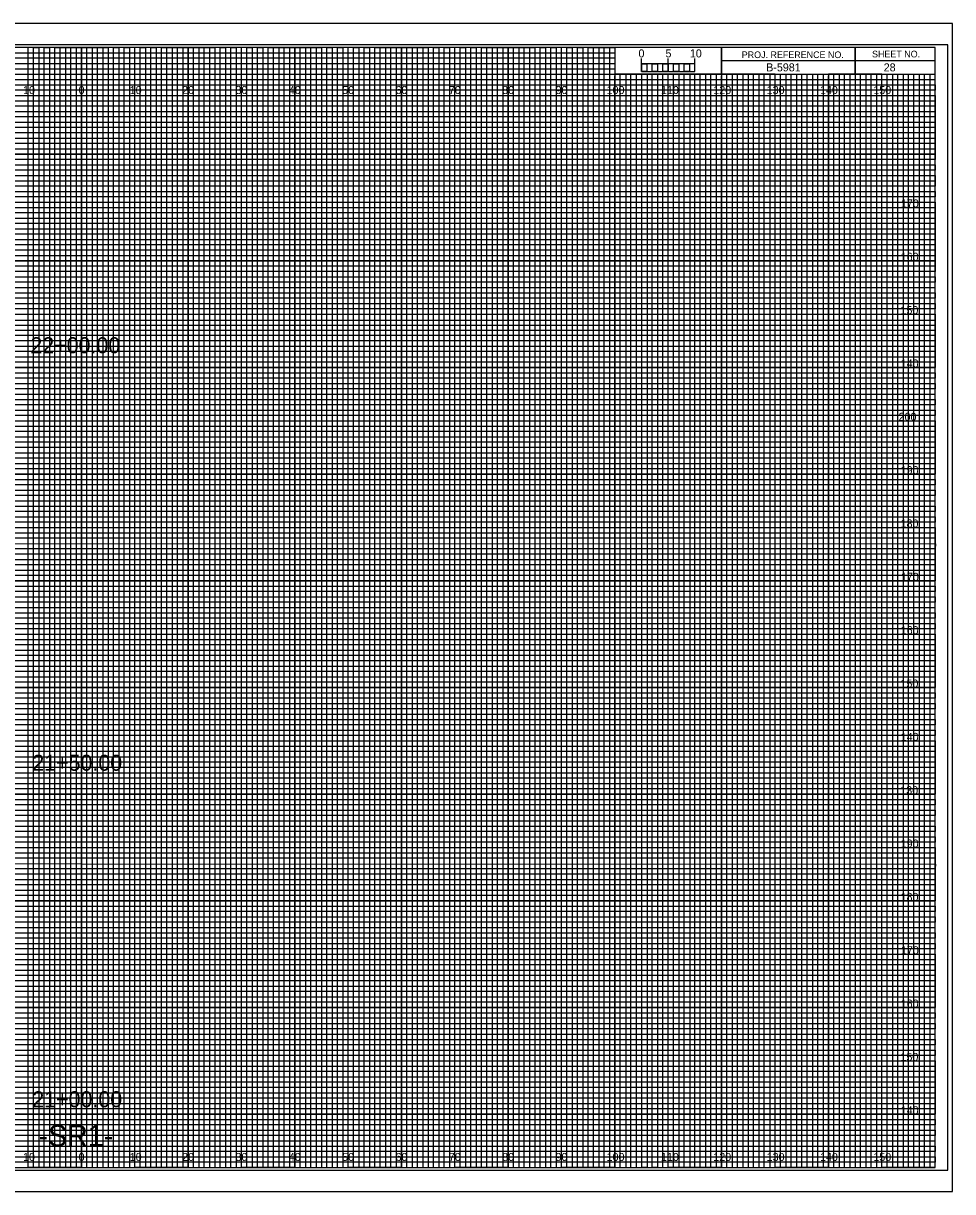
# Model space of a CAD drawing. Extents: x -13 to 323, y -5 to 654.
# Drawn here: x 149.1 to 323.3, y -4.5 to 214.5 of the extents above; entities that cross this region are included whole.
import ezdxf

# ---------------------------------------------------------------- set-up
doc = ezdxf.new("R2010")
doc.units = 0
for name, color, linetype in [('Exist Cross Section Cell', 7, 'Continuous'), ('Exist XS Center Line Elevation Label', 7, 'Continuous'), ('Exist XS Ground Line', 7, 'Continuous'), ('Prop CMT Concrete Structures', 7, 'Continuous'), ('Prop CMT Guardrail Graphics', 7, 'Continuous'), ('Prop CMT Pvmt Course 1', 7, 'Continuous'), ('Prop CMT Pvmt Course 2', 7, 'Continuous'), ('Prop CMT Pvmt Course 3', 7, 'Continuous'), ('Prop CMT Pvmt Surface', 7, 'Continuous'), ('Prop CMT Shld Paved Course 1', 7, 'Continuous'), ('Prop CMT Shld Paved Course 2', 7, 'Continuous'), ('Prop CMT Shld Paved Course 3', 7, 'Continuous'), ('Prop CMT Subgrade Earthwork', 7, 'Continuous'), ('Prop XS Ditch Standard Text', 7, 'Continuous'), ('Prop XS SE Text', 7, 'Continuous'), ('Prop XS Side Slope Text', 7, 'Continuous'), ('Scratch_Level_0', 7, 'Continuous')]:
    doc.layers.add(name, color=color, linetype=linetype)

msp = doc.modelspace()

# ---------------------------------------------------------------- linework, layer by layer
at = {"layer": 'Exist XS Center Line Elevation Label'}
for points in [[(145, 0), (155, 0), (155, 210), (165, 210), (165, 0), (175, 0), (175, 210), (185, 210), (185, 0), (195, 0), (195, 210), (205, 210), (205, 0), (215, 0), (215, 210), (225, 210), (225, 0), (235, 0), (235, 210), (245, 210), (245, 0), (255, 0), (255, 210), (259.93, 210), (260, 210), (260, 205), (264.99, 205), (264.99, 0), (275, 0), (275, 205), (285, 205), (285, 0), (295, 0), (295, 205), (305, 205), (305, 0), (315, 0), (315, 205)], [(0, 205), (275, 205)], [(0, 185), (320, 185), (320, 195), (0, 195)], [(0, 165), (320, 165), (320, 175), (0, 175)], [(0, 145), (320, 145), (320, 155), (0, 155)], [(0, 125), (320, 125), (320, 135), (0, 135)], [(0, 105), (320, 105), (320, 115), (0, 115)], [(0, 85), (320, 85), (320, 95), (0, 95)], [(0, 65), (320, 65), (320, 75), (0, 75)], [(0, 45), (320, 45), (320, 55), (0, 55)], [(0, 25), (320, 25), (320, 35), (0, 35)], [(0, 5), (320, 5), (320, 15), (0, 15)]]:
    msp.add_lwpolyline(points, dxfattribs=at)
at = {"layer": 'Exist XS Ground Line'}
for p, q in [((150, 210), (140, 210)), ((150, 0), (150, 210)), ((170, 210), (160, 210)), ((160, 210), (160, 0)), ((170, 0), (170, 210)), ((190, 210), (180, 210)), ((180, 210), (180, 0)), ((190, 0), (190, 210)), ((210, 210), (200, 210)), ((200, 210), (200, 0)), ((210, 0), (210, 210)), ((230, 210), (220, 210)), ((220, 210), (220, 0)), ((230, 0), (230, 210)), ((250, 210), (240, 210)), ((240, 210), (240, 0)), ((250, 0), (250, 210)), ((260, 210), (260, 0)), ((270, 0), (270, 205)), ((290, 205), (280, 205)), ((280, 205), (280, 0)), ((290, 0), (290, 205)), ((310, 205), (300, 205)), ((300, 205), (300, 0)), ((310, 0), (310, 205)), ((160, 0), (150, 0)), ((180, 0), (170, 0)), ((200, 0), (190, 0)), ((220, 0), (210, 0)), ((240, 0), (230, 0)), ((260, 0), (250, 0)), ((280, 0), (270, 0)), ((300, 0), (290, 0)), ((320, 0), (310, 0)), ((320, 0), (320, 0))]:
    msp.add_line(p, q, dxfattribs=at)
for points in [[(0, 200), (320, 200), (320, 190), (0, 190)], [(0, 180), (320, 180), (320, 170), (0, 170)], [(0, 160), (320, 160), (320, 150), (0, 150)], [(0, 140), (320, 140), (320, 130), (0, 130)], [(0, 120), (320, 120), (320, 110), (0, 110)], [(0, 100), (320, 100), (320, 90), (0, 90)], [(0, 80), (320, 80), (320, 70), (0, 70)], [(0, 60), (320, 60), (320, 50), (0, 50)], [(0, 40), (320, 40), (320, 30), (0, 30)], [(0, 20), (320, 20), (320, 10), (0, 10)]]:
    msp.add_lwpolyline(points, dxfattribs=at)
at = {"layer": 'Prop CMT Pvmt Course 1'}
for p, q in [((323.3, 214.5), (-13.4, 214.5)), ((-13.4, -4.5), (323.3, -4.5))]:
    msp.add_line(p, q, dxfattribs=at)
at = {"layer": 'Prop CMT Pvmt Course 2'}
msp.add_lwpolyline([(-13.4, -4.5), (323.3, -4.5), (323.3, 214.5), (-13.4, 214.5)], close=True, dxfattribs=at)
at = {"layer": 'Prop CMT Pvmt Course 3'}
msp.add_lwpolyline([(-10.8, -0.5), (322.4, -0.5), (322.4, 210.5), (-10.8, 210.5)], close=True, dxfattribs=at)
at = {"layer": 'Prop CMT Shld Paved Course 1'}
for p, q in [((305, 210), (305, 205)), ((305, 205), (305, 210)), ((280, 207.5), (280, 205)), ((320, 207.49), (280, 207.49)), ((280, 205), (320, 205))]:
    msp.add_line(p, q, dxfattribs=at)
for points in [[(320, 210), (0, 210), (0, 0), (320, 0)], [(280, 210), (260, 210), (260, 205.03), (280, 205.03)], [(320, 210), (280, 210), (280, 205), (320, 205)]]:
    msp.add_lwpolyline(points, close=True, dxfattribs=at)
at = {"layer": 'Prop CMT Shld Paved Course 2'}
for p, q in [((267, 205), (266.01, 205)), ((266.01, 205), (266.01, 0)), ((267, 0), (267, 205)), ((269, 205), (268, 205)), ((268, 205), (268, 0)), ((269, 0), (269, 205)), ((266.01, 0), (265, 0)), ((268, 0), (267, 0))]:
    msp.add_line(p, q, dxfattribs=at)
for points in [[(150, 0), (151, 0), (151, 210), (152, 210), (152, 0)], [(152, 0), (153, 0), (153, 210), (154, 210), (154, 0)], [(155, 0), (156, 0), (156, 210), (157, 210), (157, 0)], [(157, 0), (158, 0), (158, 210), (159, 210), (159, 0)], [(160, 0), (161, 0), (161, 210), (162, 210), (162, 0)], [(162, 0), (163, 0), (163, 210), (164, 210), (164, 0)], [(165, 0), (166, 0), (166, 210), (167, 210), (167, 0)], [(167, 0), (168, 0), (168, 210), (169, 210), (169, 0)], [(170, 0), (171, 0), (171, 210), (172, 210), (172, 0)], [(172, 0), (173, 0), (173, 210), (174, 210), (174, 0)], [(175, 0), (176, 0), (176, 210), (177, 210), (177, 0)], [(177, 0), (178, 0), (178, 210), (179, 210), (179, 0)], [(180, 0), (181, 0), (181, 210), (182, 210), (182, 0)], [(182, 0), (183, 0), (183, 210), (184, 210), (184, 0)], [(185, 0), (186, 0), (186, 210), (187, 210), (187, 0)], [(187, 0), (188, 0), (188, 210), (189, 210), (189, 0)], [(190, 0), (191, 0), (191, 210), (192, 210), (192, 0)], [(192, 0), (193, 0), (193, 210), (194, 210), (194, 0)], [(195, 0), (196, 0), (196, 210), (197, 210), (197, 0)], [(197, 0), (198, 0), (198, 210), (199, 210), (199, 0)], [(200, 0), (201, 0), (201, 210), (202, 210), (202, 0)], [(202, 0), (203, 0), (203, 210), (204, 210), (204, 0)], [(205, 0), (206, 0), (206, 210), (207, 210), (207, 0)], [(207, 0), (208, 0), (208, 210), (209, 210), (209, 0)], [(210, 0), (211, 0), (211, 210), (212, 210), (212, 0)], [(212, 0), (213, 0), (213, 210), (214, 210), (214, 0)], [(215, 0), (216, 0), (216, 210), (217, 210), (217, 0)], [(217, 0), (218, 0), (218, 210), (219, 210), (219, 0)], [(220, 0), (221, 0), (221, 210), (222, 210), (222, 0)], [(222, 0), (223, 0), (223, 210), (224, 210), (224, 0)], [(225, 0), (226, 0), (226, 210), (227, 210), (227, 0)], [(227, 0), (228, 0), (228, 210), (229, 210), (229, 0)], [(230, 0), (231, 0), (231, 210), (232, 210), (232, 0)], [(232, 0), (233, 0), (233, 210), (234, 210), (234, 0)], [(235, 0), (236, 0), (236, 210), (237, 210), (237, 0)], [(237, 0), (238, 0), (238, 210), (239, 210), (239, 0)], [(240, 0), (241, 0), (241, 210), (242, 210), (242, 0)], [(242, 0), (243, 0), (243, 210), (244, 210), (244, 0)], [(245, 0), (246, 0), (246, 210), (247, 210), (247, 0)], [(247, 0), (248, 0), (248, 210), (249, 210), (249, 0)], [(250, 0), (251, 0), (251, 210), (252, 210), (252, 0)], [(252, 0), (253, 0), (253, 210), (254, 210), (254, 0)], [(255, 0), (256, 0), (256, 210), (257, 210), (257, 0)], [(257, 0), (258, 0), (258, 210), (259, 210), (259, 0)], [(260, 0), (261, 0), (261, 205), (262.02, 205), (262.02, 0)], [(262, 0), (263, 0), (263, 205), (263.99, 205), (263.99, 0)], [(270, 0), (270.98, 0), (270.98, 205), (272, 205), (272, 0)], [(272, 0), (273, 0), (273, 205), (274.05, 205), (274.05, 0)], [(275, 0), (276, 0), (276, 205), (277, 205), (277, 0)], [(277, 0), (278, 0), (278, 205), (279, 205), (279, 0)], [(280, 0), (281, 0), (281, 205), (282, 205), (282, 0)], [(282, 0), (283, 0), (283, 205), (284, 205), (284, 0)], [(285, 0), (286, 0), (286, 205), (287, 205), (287, 0)], [(287, 0), (288, 0), (288, 205), (289, 205), (289, 0)], [(290, 0), (291, 0), (291, 205), (292, 205), (292, 0)], [(292, 0), (293, 0), (293, 205), (294, 205), (294, 0)], [(295, 0), (296, 0), (296, 205), (297, 205), (297, 0)], [(297, 0), (298, 0), (298, 205), (299, 205), (299, 0)], [(300, 0), (301, 0), (301, 205), (302, 205), (302, 0)], [(302, 0), (303, 0), (303, 205), (304, 205), (304, 0)], [(305, 0), (306, 0), (306, 205), (307, 205), (307, 0)], [(307, 0), (308, 0), (308, 205), (309, 205), (309, 0)], [(310, 0), (311, 0), (311, 205), (312, 205), (312, 0)], [(312, 0), (313, 0), (313, 205), (314, 205), (314, 0)], [(315, 0), (316, 0), (316, 205), (317, 205), (317, 0)], [(317, 0), (318, 0), (318, 205), (319, 205), (319, 0)]]:
    msp.add_lwpolyline(points, dxfattribs=at)
at = {"layer": 'Prop CMT Shld Paved Course 3'}
for p, q in [((265, 205.49), (265, 207.9)), ((265, 206.9), (265, 207.9)), ((270, 205.49), (270, 207.9)), ((275, 205.49), (275, 207.9)), ((275, 206.9), (275, 207.9))]:
    msp.add_line(p, q, dxfattribs=at)
for points in [[(275, 206.9), (265, 206.9), (265, 205.49), (275, 205.49)], [(265, 206.9), (266, 206.9), (266, 205.49), (265, 205.49)], [(267, 206.9), (268, 206.9), (268, 205.49), (267, 205.49)], [(269, 206.9), (270, 206.9), (270, 205.49), (269, 205.49)], [(271, 206.9), (272, 206.9), (272, 205.49), (271, 205.49)], [(273, 206.9), (274, 206.9), (274, 205.49), (273, 205.49)]]:
    msp.add_lwpolyline(points, close=True, dxfattribs=at)
at = {"layer": 'Prop CMT Subgrade Earthwork'}
for p, q in [((150, 0), (150, 210)), ((160, 0), (160, 210)), ((170, 0), (170, 210)), ((180, 0), (180, 210)), ((190, 0), (190, 210)), ((200, 0), (200, 210)), ((210, 0), (210, 210)), ((220, 0), (220, 210)), ((230, 0), (230, 210)), ((240, 0), (240, 210)), ((250, 0), (250, 210)), ((260, 0), (260, 204.69)), ((270, 0), (270, 204.69)), ((280, 0), (280, 204.69)), ((290, 0), (290, 204.69)), ((300, 0), (300, 204.69)), ((310, 0), (310, 204.69)), ((0, 200), (320, 200)), ((0, 190), (320, 190)), ((0, 180), (320, 180)), ((0, 170), (320, 170)), ((0, 160), (320, 160)), ((0, 150), (320, 150)), ((0, 140), (320, 140)), ((0, 130), (320, 130)), ((0, 120), (320, 120)), ((0, 110), (320, 110)), ((0, 100), (320, 100)), ((0, 90), (320, 90)), ((0, 80), (320, 80)), ((0, 70), (320, 70)), ((0, 60), (320, 60)), ((0, 50), (320, 50)), ((0, 40), (320, 40)), ((0, 30), (320, 30)), ((0, 20), (320, 20)), ((0, 10), (320, 10))]:
    msp.add_line(p, q, dxfattribs=at)
at = {"layer": 'Scratch_Level_0'}
for p, q in [((0, 209), (260, 209)), ((260, 209), (260, 207.98)), ((260, 207.98), (0, 207.98)), ((0, 207), (260, 207)), ((260, 205.89), (0, 205.89)), ((260, 207), (260, 205.89)), ((0, 204), (320, 204))]:
    msp.add_line(p, q, dxfattribs=at)
for points in [[(0, 203), (270, 203), (320, 203), (320, 202), (0, 202)], [(0, 201), (320, 201), (320, 199), (0, 199)], [(0, 198), (320, 198), (320, 197), (0, 196.98)], [(0, 196), (320, 196), (320, 194), (0, 194)], [(0, 193), (320, 193), (320, 192), (0, 192)], [(0, 191), (320, 191), (320, 189), (0, 189)], [(0, 188), (320, 188), (320, 187), (0, 187)], [(0, 186), (320, 186), (320, 184), (0, 184)], [(0, 183), (320, 183), (320, 182), (0, 182)], [(0, 181), (320, 181), (320, 179), (0, 179)], [(0, 178), (320, 178), (320, 177), (0, 177)], [(0, 176), (320, 176), (320, 173.95), (320, 173), (320, 172), (0, 172)], [(0, 174), (320, 174), (320, 173), (0, 173)], [(0, 171), (320, 171), (320, 169), (0, 169.03)], [(0, 169.03), (320, 169), (320, 168), (0, 168)], [(0, 167), (320, 167), (320, 166), (0, 166)], [(0, 164), (320, 164), (320, 163), (0, 163)], [(0, 162), (320, 162), (320, 161), (0, 161)], [(-0.07, 158.89), (320, 158.89), (320, 157.88), (-0.07, 157.88)], [(0, 157), (320, 157), (320, 156), (0, 156)], [(0, 154), (320, 154), (320, 153), (0, 153)], [(0, 152), (320, 152), (320, 151), (0, 151)], [(0, 149), (320, 149), (320, 148), (0, 148)], [(0, 147), (320, 147), (320, 146), (0, 146)], [(0, 144), (320, 144), (320, 143), (0, 143)], [(0, 142), (320, 142), (320, 141), (0, 141)], [(0, 139), (320, 139), (319.99, 137.98), (0, 138)], [(0, 137), (320, 137), (320, 136), (0, 136)], [(0, 134), (320, 134), (320, 133), (0, 133)], [(0, 132), (320, 132), (320, 131), (0, 131)], [(0, 129), (320, 129), (320, 128), (0, 128)], [(0, 127), (320, 127), (320, 126), (0, 126)], [(0, 124), (320, 124), (320, 123), (0, 123)], [(0, 122), (320, 122), (320, 121), (0, 121)], [(0, 119), (320, 119), (320, 118), (0, 118)], [(0, 116.99), (320.07, 116.91), (320, 116), (0, 116)], [(0, 114), (320, 114), (320, 113), (0, 113)], [(0, 112), (320, 112), (320, 111), (0, 111)], [(0, 109), (320, 109), (320, 108), (0, 108)], [(0, 107), (320, 107), (320, 106), (0, 106)], [(0, 104), (320, 104), (320, 103), (0, 103)], [(0, 102), (320, 102), (320, 101), (0, 101)], [(0, 99), (320, 99), (320, 98), (0, 98)], [(0, 97), (320, 97), (320, 96), (0, 96)], [(0, 94), (320, 94), (320, 93), (0, 93)], [(0, 92), (320, 92), (320, 91), (0, 91)], [(0, 89), (320, 89), (320, 88), (0, 88)], [(0, 87), (320, 87), (320, 86), (0, 86)], [(0, 84), (320, 84), (320, 83), (0, 83)], [(0, 82), (320, 82), (320, 81), (0, 81)], [(0, 79), (320, 79), (319.99, 77.98), (0, 78)], [(0, 77), (320, 77), (320, 76), (0, 76)], [(0, 74), (320, 74), (320, 73), (0, 73)], [(0, 72), (320, 72), (320, 71), (0, 71)], [(0, 69), (320, 69), (320, 68), (0, 68)], [(0, 67), (320, 67), (320, 66), (0, 66)], [(0, 64), (320, 64), (320, 63), (0, 63)], [(0, 62), (320, 62), (320, 61), (0, 61)], [(0, 59), (320, 59), (320, 58), (0, 58)], [(0, 56.99), (320.07, 56.91), (320, 56), (0, 56)], [(0, 54), (320, 54), (320, 53), (0, 53)], [(0, 52), (320, 52), (320, 51), (0, 51)], [(0, 49), (320, 49), (320, 48), (0, 48)], [(0, 47), (320, 47), (320, 46), (0, 46)], [(0, 44), (320, 44), (320, 43), (0, 43)], [(0, 42), (320, 42), (320, 41), (0, 41)], [(0, 39), (320, 39), (320, 38), (0, 38)], [(0, 37), (320, 37), (320, 36), (0, 36)], [(0, 34), (320, 34), (320, 33), (0, 33)], [(0, 32), (320, 32), (320, 31), (0, 31)], [(0, 29), (320, 29), (320, 28), (0, 28)], [(0, 27), (320, 27), (320, 26), (0, 26)], [(0, 24), (320, 24), (320, 23), (0, 23)], [(0, 22), (320, 22), (320, 21), (0, 21)], [(0, 19), (320, 19), (320, 18), (0, 18)], [(0, 17), (320, 17), (320, 16), (0, 16)], [(0, 14), (320, 14), (320, 13), (0, 13)], [(0, 12), (320, 12), (320, 11), (0, 11)], [(0, 9), (320, 9), (320, 8), (0, 8)], [(0, 7), (320, 7), (320, 6), (0, 6)], [(0, 4), (320, 4), (320, 3), (0, 3)], [(0, 2), (320, 2), (320, 1), (0, 1)]]:
    msp.add_lwpolyline(points, dxfattribs=at)

# ---------------------------------------------------------------- texts
at = {"layer": 'Exist Cross Section Cell'}
for s, p in [('10', (149.04, 201.25)), ('0', (159.45, 201.25)), ('0', (159.45, 201.25)), ('10', (169.04, 201.25)), ('20', (178.86, 201.25)), ('30', (188.86, 201.25)), ('40', (198.86, 201.25)), ('50', (208.86, 201.25)), ('60', (218.86, 201.25)), ('70', (228.86, 201.25)), ('80', (238.86, 201.25)), ('90', (248.86, 201.25)), ('100', (258.44, 201.25)), ('110', (268.62, 201.25)), ('120', (278.44, 201.25)), ('130', (288.44, 201.25)), ('140', (298.44, 201.25)), ('150', (308.44, 201.25)), ('10', (149.04, 1.25)), ('0', (159.45, 1.25)), ('0', (159.45, 1.25)), ('10', (169.04, 1.25)), ('20', (178.86, 1.25)), ('30', (188.86, 1.25)), ('40', (198.86, 1.25)), ('50', (208.86, 1.25)), ('60', (218.86, 1.25)), ('70', (228.86, 1.25)), ('80', (238.86, 1.25)), ('90', (248.86, 1.25)), ('100', (258.44, 1.25)), ('110', (268.62, 1.25)), ('120', (278.44, 1.25)), ('130', (288.44, 1.25)), ('140', (298.44, 1.25)), ('150', (308.44, 1.25))]:
    msp.add_text(s, height=1.5, dxfattribs=at).set_placement(p)
at = {"layer": 'Prop CMT Concrete Structures'}
for s, p in [('22+00.00', (150.41, 152.66)), ('21+50.00', (150.77, 74.4)), ('21+00.00', (150.77, 11.32))]:
    msp.add_text(s, height=3, dxfattribs=at).set_placement(p)
at = {"layer": 'Prop CMT Guardrail Graphics'}
for s, p in [('170', (313.61, 180)), ('160', (313.57, 170)), ('150', (313.52, 160)), ('140', (313.57, 150)), ('200', (313.17, 140)), ('190', (313.57, 130)), ('180', (313.55, 120)), ('170', (313.61, 110)), ('160', (313.57, 100)), ('150', (313.52, 90)), ('140', (313.57, 80)), ('130', (313.49, 70)), ('190', (313.57, 60)), ('180', (313.55, 50)), ('170', (313.61, 40)), ('160', (313.57, 30)), ('150', (313.52, 20)), ('140', (313.57, 10))]:
    msp.add_text(s, height=1.5, dxfattribs=at).set_placement(p)
at = {"layer": 'Prop CMT Pvmt Surface'}
for s, p in [('5', (269.47, 208.12)), ('10', (274.04, 208.12))]:
    msp.add_text(s, height=1.5, dxfattribs=at).set_placement(p)
at = {"layer": 'Prop CMT Shld Paved Course 1'}
for s, p in [('PROJ. REFERENCE NO.', (283.77, 207.99)), ('SHEET NO.', (308.19, 208.12))]:
    msp.add_text(s, height=1.25, dxfattribs=at).set_placement(p)
at = {"layer": 'Prop CMT Shld Paved Course 3'}
msp.add_text('0', height=1.5, dxfattribs=at).set_placement((264.41, 208.12))
at = {"layer": 'Prop XS Ditch Standard Text'}
msp.add_text('-SR1-', height=4, dxfattribs=at).set_placement((151.95, 4))
at = {"layer": 'Prop XS SE Text'}
msp.add_text(' B-5981', height=1.5, dxfattribs=at).set_placement((287.79, 205.5))
at = {"layer": 'Prop XS Side Slope Text'}
msp.add_text('28', height=1.5, dxfattribs=at).set_placement((310.38, 205.5))

doc.saveas('drawing.dxf')
